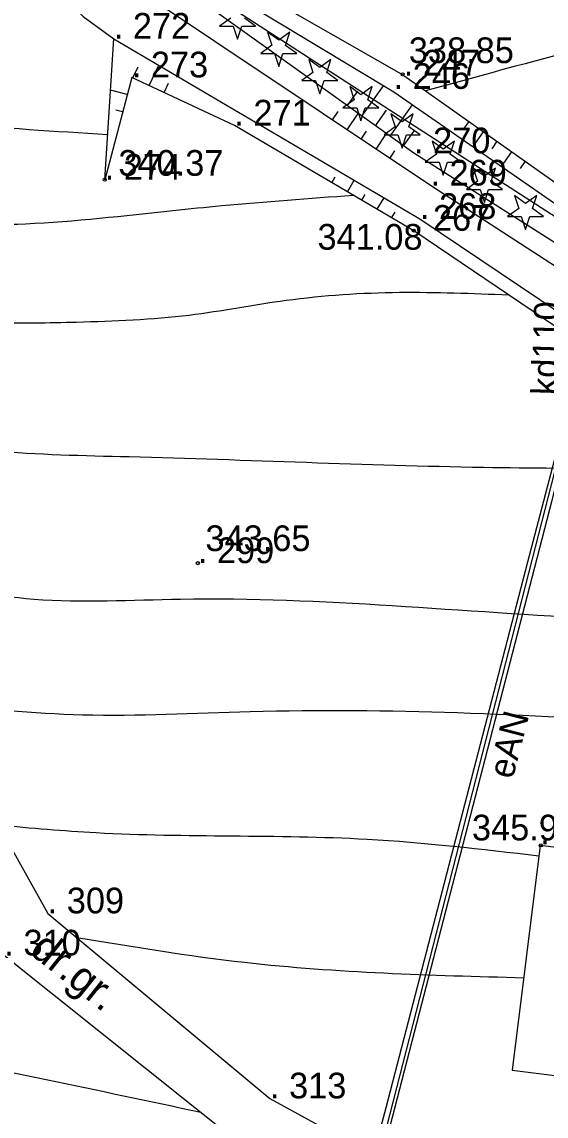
# Model space of a CAD drawing. Extents: x 4632591 to 4653165, y 5351032 to 5369868.
# Drawn here: x 4644617.6 to 4644648.3, y 5358359.7 to 5358423.6 of the extents above; entities that cross this region are included whole.
import ezdxf

# ---------------------------------------------------------------- set-up
doc = ezdxf.new("R2010")
doc.units = 0
for name, color, linetype in [('EBUPP_312', 7, 'Continuous'), ('EUZPU_424', 7, 'Continuous'), ('SZZTZ_925', 7, 'Continuous'), ('UEEPO_585', 7, 'Continuous'), ('UKKPB_562', 7, 'Continuous'), ('Warstwa 62', 7, 'Continuous'), ('WUKPS_403', 7, 'Continuous'), ('WUKPS_820', 7, 'Continuous'), ('WUKPS_823', 7, 'Continuous'), ('WUKPS_824', 7, 'Continuous'), ('WWRPH_811', 7, 'Continuous')]:
    doc.layers.add(name, color=color, linetype=linetype)

msp = doc.modelspace()

# ---------------------------------------------------------------- linework, layer by layer
at = {"layer": 'EBUPP_312'}
msp.add_lwpolyline([(4644647.911, 5358375.479), (4644646.282, 5358362.362), (4644651.581, 5358361.704), (4644653.21, 5358374.821)], close=True, dxfattribs=at)
at = {"layer": 'EUZPU_424'}
for points in [[(4644607.61, 5358432.17), (4644607.56, 5358392.86), (4644609.22, 5358382.47), (4644616.62, 5358369.06), (4644630.54, 5358357.95), (4644642.13, 5358351.82), (4644658.623, 5358347.91), (4644680.806, 5358342.063)], [(4644612.98, 5358431.93), (4644621.22, 5358423.87), (4644623.01, 5358422.57)], [(4644675.121, 5358297.602), (4644676.248, 5358300.881), (4644677.005, 5358304.092), (4644679.073, 5358313.341), (4644680.722, 5358320.714), (4644680.919, 5358321.592), (4644681.429, 5358324.885), (4644682.537, 5358331.059), (4644684.504, 5358343.896), (4644686.022, 5358352.777), (4644686.732, 5358361.758), (4644688.28, 5358374.66), (4644687.59, 5358381.7), (4644684.88, 5358385.07), (4644678.84, 5358389.1), (4644673.9, 5358392.63), (4644663.63, 5358399.66), (4644641.5, 5358414), (4644622.58, 5358426.64)], [(4644610.341, 5358417.956), (4644610.89, 5358393.08), (4644612.64, 5358383.16), (4644619.15, 5358371.52), (4644632.13, 5358360.72), (4644643.742, 5358354.359), (4644681.288, 5358345.24)]]:
    msp.add_lwpolyline(points, dxfattribs=at)
at = {"layer": 'SZZTZ_925'}
for p, q in [((4644629.835, 5358423.769), (4644629.186, 5358423.297)), ((4644629.186, 5358423.297), (4644629.988, 5358423.297)), ((4644629.988, 5358423.297), (4644630.237, 5358422.533)), ((4644630.237, 5358422.533), (4644630.485, 5358423.297)), ((4644630.485, 5358423.297), (4644631.288, 5358423.297)), ((4644631.288, 5358423.297), (4644630.638, 5358423.768)), ((4644632.64, 5358422.474), (4644631.99, 5358422.946)), ((4644631.99, 5358422.946), (4644632.238, 5358422.182)), ((4644633.29, 5358422.946), (4644632.64, 5358422.474)), ((4644633.041, 5358422.181), (4644633.29, 5358422.946)), ((4644632.238, 5358422.182), (4644631.589, 5358421.71)), ((4644633.691, 5358421.71), (4644633.041, 5358422.181)), ((4644631.589, 5358421.71), (4644632.391, 5358421.71)), ((4644632.391, 5358421.71), (4644632.64, 5358420.946)), ((4644632.64, 5358420.946), (4644632.888, 5358421.71)), ((4644632.888, 5358421.71), (4644633.691, 5358421.71)), ((4644635.042, 5358420.887), (4644634.392, 5358421.359)), ((4644634.392, 5358421.359), (4644634.64, 5358420.595)), ((4644635.692, 5358421.359), (4644635.042, 5358420.887)), ((4644635.443, 5358420.594), (4644635.692, 5358421.359)), ((4644634.64, 5358420.595), (4644633.991, 5358420.123)), ((4644633.991, 5358420.123), (4644634.793, 5358420.123)), ((4644634.793, 5358420.123), (4644635.042, 5358419.359)), ((4644635.042, 5358419.359), (4644635.29, 5358420.123)), ((4644635.29, 5358420.123), (4644636.093, 5358420.123)), ((4644636.093, 5358420.123), (4644635.443, 5358420.594)), ((4644637.445, 5358419.3), (4644636.795, 5358419.772)), ((4644636.795, 5358419.772), (4644637.043, 5358419.008)), ((4644638.095, 5358419.772), (4644637.445, 5358419.3)), ((4644637.846, 5358419.007), (4644638.095, 5358419.772)), ((4644637.043, 5358419.008), (4644636.394, 5358418.536)), ((4644638.496, 5358418.536), (4644637.846, 5358419.007)), ((4644636.394, 5358418.536), (4644637.196, 5358418.536)), ((4644637.196, 5358418.536), (4644637.445, 5358417.772)), ((4644637.445, 5358417.772), (4644637.693, 5358418.536)), ((4644637.693, 5358418.536), (4644638.496, 5358418.536)), ((4644639.847, 5358417.713), (4644639.197, 5358418.185)), ((4644639.197, 5358418.185), (4644639.445, 5358417.421)), ((4644640.497, 5358418.185), (4644639.847, 5358417.713)), ((4644640.248, 5358417.42), (4644640.497, 5358418.185)), ((4644639.445, 5358417.421), (4644638.796, 5358416.949)), ((4644638.796, 5358416.949), (4644639.598, 5358416.949)), ((4644639.598, 5358416.949), (4644639.847, 5358416.185)), ((4644639.847, 5358416.185), (4644640.095, 5358416.949)), ((4644640.095, 5358416.949), (4644640.898, 5358416.949)), ((4644640.898, 5358416.949), (4644640.248, 5358417.42)), ((4644642.25, 5358416.126), (4644641.6, 5358416.598)), ((4644641.6, 5358416.598), (4644641.848, 5358415.834)), ((4644642.9, 5358416.598), (4644642.25, 5358416.126)), ((4644642.651, 5358415.833), (4644642.9, 5358416.598)), ((4644641.848, 5358415.834), (4644641.199, 5358415.362)), ((4644643.301, 5358415.362), (4644642.651, 5358415.833)), ((4644641.199, 5358415.362), (4644642.001, 5358415.362)), ((4644642.001, 5358415.362), (4644642.25, 5358414.598)), ((4644642.25, 5358414.598), (4644642.498, 5358415.362)), ((4644642.498, 5358415.362), (4644643.301, 5358415.362)), ((4644644.652, 5358414.539), (4644644.002, 5358415.011)), ((4644644.002, 5358415.011), (4644644.25, 5358414.247)), ((4644645.302, 5358415.011), (4644644.652, 5358414.539)), ((4644645.053, 5358414.246), (4644645.302, 5358415.011)), ((4644644.25, 5358414.247), (4644643.601, 5358413.775)), ((4644645.703, 5358413.775), (4644645.053, 5358414.246)), ((4644643.601, 5358413.775), (4644644.403, 5358413.775)), ((4644644.403, 5358413.775), (4644644.652, 5358413.011)), ((4644644.652, 5358413.011), (4644644.9, 5358413.775)), ((4644644.9, 5358413.775), (4644645.703, 5358413.775)), ((4644647.055, 5358412.952), (4644646.405, 5358413.424)), ((4644646.405, 5358413.424), (4644646.653, 5358412.66)), ((4644647.705, 5358413.424), (4644647.055, 5358412.952)), ((4644647.456, 5358412.659), (4644647.705, 5358413.424)), ((4644646.653, 5358412.66), (4644646.004, 5358412.188)), ((4644648.106, 5358412.188), (4644647.456, 5358412.659)), ((4644646.004, 5358412.188), (4644646.806, 5358412.188)), ((4644646.806, 5358412.188), (4644647.055, 5358411.424)), ((4644647.055, 5358411.424), (4644647.303, 5358412.188)), ((4644647.303, 5358412.188), (4644648.106, 5358412.188))]:
    msp.add_line(p, q, dxfattribs=at)
at = {"layer": 'UEEPO_585'}
for points in [[(4644654.756, 5358408.317), (4644637.887, 5358419.204), (4644615.627, 5358433.571), (4644614.206, 5358434.487), (4644594.947, 5358438.482), (4644591.953, 5358439.845), (4644585.885, 5358446.338)], [(4644650.142, 5358401.904), (4644648.58, 5358395.615), (4644643.098, 5358374.419), (4644638.137, 5358355.239), (4644635.919, 5358347.404), (4644644.383, 5358342.569)]]:
    msp.add_lwpolyline(points, dxfattribs=at)
at = {"layer": 'UKKPB_562'}
for points in [[(4644649.847, 5358347.193), (4644638.766, 5358358.294), (4644649.178, 5358398.883), (4644649.282, 5358402.17), (4644649.384, 5358405.504), (4644649.518, 5358410.278)], [(4644650.933, 5358405.165), (4644650.513, 5358404.579), (4644649.041, 5358399.141), (4644647.168, 5358392.017), (4644638.892, 5358360.165), (4644635.803, 5358348.552), (4644635.322, 5358347.088), (4644631.247, 5358331.424), (4644626.088, 5358311.848)]]:
    msp.add_lwpolyline(points, dxfattribs=at)
at = {"layer": 'WUKPS_403'}
for centre in [(4644639.872, 5358420.49), (4644639.872, 5358420.49), (4644622.48, 5358414.34), (4644640.523, 5358411.371), (4644627.92, 5358391.96), (4644647.949, 5358375.486)]:
    msp.add_circle(centre, 0.09, dxfattribs=at)
at = {"layer": 'WUKPS_820'}
for p, q in [((4644624.127, 5358420.278), (4644624.429, 5358420.921)), ((4644625.07, 5358419.836), (4644625.631, 5358421.033)), ((4644625.945, 5358419.426), (4644626.206, 5358419.983)), ((4644623.794, 5358419.303), (4644622.816, 5358419.562)), ((4644636.649, 5358418.662), (4644637.258, 5358419.514)), ((4644637.5, 5358418.054), (4644638.767, 5358419.825)), ((4644639.142, 5358416.88), (4644640.455, 5358418.717)), ((4644623.527, 5358418.296), (4644623.138, 5358418.399)), ((4644635.774, 5358417.825), (4644636.105, 5358418.32)), ((4644636.646, 5358417.243), (4644637.289, 5358418.206)), ((4644638.29, 5358417.489), (4644638.943, 5358418.401)), ((4644643.733, 5358417.745), (4644643.424, 5358417.307)), ((4644637.455, 5358416.703), (4644637.768, 5358417.171)), ((4644638.326, 5358416.121), (4644638.933, 5358417.029)), ((4644639.932, 5358416.315), (4644640.593, 5358417.239)), ((4644644.589, 5358417.14), (4644643.976, 5358416.272)), ((4644645.384, 5358416.579), (4644645.08, 5358416.148)), ((4644639.135, 5358415.58), (4644639.43, 5358416.022)), ((4644646.241, 5358415.975), (4644645.637, 5358415.119)), ((4644647.036, 5358415.414), (4644646.736, 5358414.989)), ((4644635.743, 5358414.165), (4644635.942, 5358414.504)), ((4644636.649, 5358413.634), (4644637.045, 5358414.311)), ((4644637.49, 5358413.141), (4644637.687, 5358413.479)), ((4644638.395, 5358412.611), (4644638.79, 5358413.285)), ((4644639.236, 5358412.118), (4644639.433, 5358412.454))]:
    msp.add_line(p, q, dxfattribs=at)
at = {"layer": 'WUKPS_823'}
for points in [[(4644639.94, 5358420.42), (4644623.03, 5358430.09), (4644638.84, 5358436.33), (4644647.86, 5358440.19), (4644656.49, 5358446.28), (4644661.65, 5358451.39), (4644679.02, 5358468.91)], [(4644682.827, 5358382.95), (4644666.895, 5358393.772), (4644661.93, 5358397.145), (4644650.27, 5358404.772), (4644640.53, 5358411.36), (4644630.05, 5358417.5), (4644624.06, 5358420.31), (4644622.48, 5358414.34)], [(4644639.94, 5358420.42), (4644656.946, 5358408.423), (4644667.513, 5358400.969)]]:
    msp.add_lwpolyline(points, dxfattribs=at)
at = {"layer": 'WUKPS_824'}
for points in [[(4644666.89, 5358400.78), (4644664.19, 5358400.86), (4644640.54, 5358415.88), (4644623.03, 5358428.4), (4644620.787, 5358430.651)], [(4644620.787, 5358430.651), (4644639.361, 5358419.468), (4644656.41, 5358407.65), (4644666.437, 5358400.793)], [(4644622.48, 5358414.34), (4644623.01, 5358422.57), (4644640.89, 5358412.05), (4644654.945, 5358402.602), (4644662.66, 5358397.41), (4644672.9, 5358390.717), (4644680.323, 5358385.058), (4644682.827, 5358382.95)]]:
    msp.add_lwpolyline(points, dxfattribs=at)
at = {"layer": 'WWRPH_811'}
for points in [[(4644627.307, 5358427.644), (4644633.608, 5358428.776), (4644646.157, 5358429.837), (4644652.95, 5358429.346), (4644656.337, 5358428.906), (4644658.031, 5358428.689), (4644659.726, 5358428.492), (4644664.602, 5358427.986), (4644667.035, 5358427.695), (4644668.25, 5358427.526), (4644669.463, 5358427.336), (4644672.439, 5358426.722), (4644675.371, 5358425.926), (4644678.274, 5358425.019), (4644681.163, 5358424.071), (4644687.248, 5358422.076), (4644687.736, 5358421.913)], [(4644685.634, 5358417.328), (4644683.469, 5358417.979), (4644682.386, 5358418.307), (4644681.299, 5358418.619), (4644675.194, 5358420.249), (4644672.127, 5358421.035), (4644669.03, 5358421.813), (4644666.326, 5358422.438), (4644663.609, 5358422.937), (4644660.888, 5358423.258), (4644659.529, 5358423.335), (4644658.85, 5358423.35), (4644658.172, 5358423.348), (4644654.85, 5358423.026), (4644651.566, 5358422.296), (4644641.218, 5358419.519)], [(4644610.341, 5358417.956), (4644611.377, 5358417.834), (4644611.901, 5358417.774), (4644612.427, 5358417.717), (4644613.48, 5358417.623), (4644622.65, 5358416.974)], [(4644610.478, 5358411.771), (4644617.86, 5358411.771), (4644626.467, 5358412.543), (4644629.312, 5358412.828), (4644636.986, 5358413.437)], [(4644610.593, 5358406.561), (4644615.935, 5358406.032), (4644620.834, 5358406.032), (4644627.414, 5358406.441), (4644633.075, 5358407.303), (4644639.696, 5358407.767), (4644646.065, 5358407.617)], [(4644661.328, 5358397.539), (4644644.594, 5358397.539), (4644623.911, 5358398.157), (4644615.924, 5358398.518), (4644610.755, 5358399.183)], [(4644611.261, 5358390.978), (4644618.338, 5358389.864), (4644626.912, 5358389.864), (4644651.608, 5358388.727), (4644674.42, 5358388.66)], [(4644612.531, 5358383.776), (4644621.176, 5358383.112), (4644630.975, 5358383.301), (4644655.186, 5358382.614), (4644665.449, 5358381.951), (4644684.416, 5358381.35)], [(4644647.834, 5358374.863), (4644637.8, 5358375.831), (4644621.975, 5358376.212), (4644616.277, 5358376.656)], [(4644620.834, 5358370.119), (4644630.651, 5358368.665), (4644646.953, 5358367.766)], [(4644628.098, 5358359.899), (4644610.008, 5358363.599), (4644605.752, 5358364.351), (4644601.468, 5358364.946), (4644597.175, 5358365.491), (4644592.892, 5358366.094)]]:
    msp.add_spline(points, degree=3, dxfattribs=at)

# ---------------------------------------------------------------- texts
at = {"layer": 'EUZPU_424'}
msp.add_text('dr.gr.', height=1.8, rotation=321.40551, dxfattribs=at).set_placement((4644618.023, 5358369.214))
at = {"layer": 'UEEPO_585'}
msp.add_text('eAN', height=1.5, rotation=75.49573, dxfattribs=at).set_placement((4644646.298, 5358379.305))
at = {"layer": 'UKKPB_562'}
msp.add_text('kd110', height=1.5, rotation=88.25885, dxfattribs=at).set_placement((4644648.895, 5358401.754))
at = {"layer": 'Warstwa 62'}
for s, p in [('. 272', (4644623.01, 5358422.57)), ('. 247', (4644639.94, 5358420.42)), ('. 273', (4644624.06, 5358420.31)), ('. 246', (4644639.35, 5358419.64)), ('. 271', (4644630.05, 5358417.5)), ('. 270', (4644640.54, 5358415.88)), ('. 274', (4644622.48, 5358414.34)), ('. 269', (4644641.5, 5358414)), ('. 268', (4644640.89, 5358412.05)), ('. 267', (4644640.53, 5358411.36)), ('. 299', (4644627.92, 5358391.96)), ('. 303', (4644647.91, 5358375.54)), ('. 309', (4644619.15, 5358371.52)), ('. 310', (4644616.62, 5358369.06)), ('. 313', (4644632.13, 5358360.72))]:
    msp.add_text(s, height=1.5, dxfattribs=at).set_placement(p)
at = {"layer": 'WUKPS_403'}
for s, p in [('338.85', (4644640.237, 5358421.143)), ('340.37', (4644623.278, 5358414.569)), ('341.08', (4644634.905, 5358410.254)), ('343.65', (4644628.361, 5358392.664)), ('345.97', (4644643.925, 5358375.778))]:
    msp.add_text(s, height=1.5, dxfattribs=at).set_placement(p)

doc.saveas('drawing.dxf')
